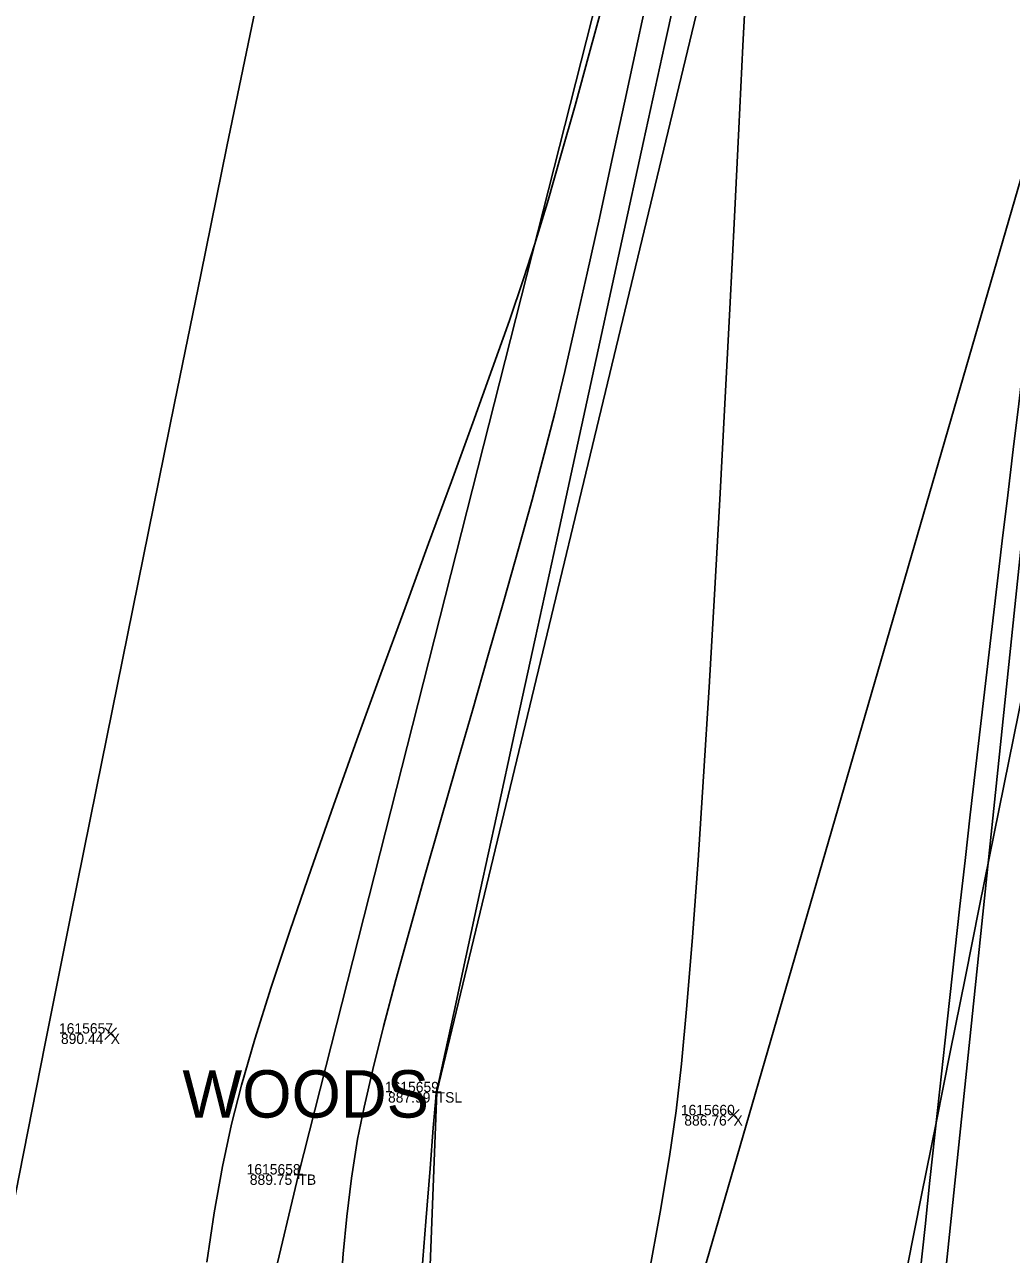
# Model space of a CAD drawing. Extents: x 1957117 to 1971063, y 701601 to 715861.
# Drawn here: x 1962847.45 to 1962880.75, y 704038.02 to 704079.53 of the extents above; entities that cross this region are included whole.
import ezdxf

# ---------------------------------------------------------------- set-up
doc = ezdxf.new("R2010")
doc.units = 0
for name, color, linetype in [('AP_X_Lights', 7, 'Continuous'), ('DT_X_Break_Line', 7, 'Continuous'), ('DT_X_Contour_Major', 7, 'Continuous'), ('DT_X_Contour_Minor', 7, 'Continuous'), ('DT_X_TIN_Hull', 7, 'Continuous'), ('GE_X_CL_20', 7, 'Continuous'), ('HY_X_Water_Edge', 7, 'Continuous'), ('PV_P_Drive', 7, 'Continuous'), ('PV_P_Shoulder', 7, 'Continuous'), ('RS_Raster1', 7, 'Continuous'), ('RW_X_Esmt_RR', 7, 'Continuous'), ('RW_X_Fee_RW', 7, 'Continuous'), ('SC_Scratch1', 7, 'Continuous'), ('VG_X_Text', 7, 'Continuous')]:
    doc.layers.add(name, color=color, linetype=linetype)

msp = doc.modelspace()

# ---------------------------------------------------------------- linework, layer by layer
at = {"layer": 'AP_X_Lights'}
for p, q in [((1962850.162, 704045.276), (1962850.55, 704045.666)), ((1962850.162, 704045.666), (1962850.55, 704045.276)), ((1962871.181, 704042.521), (1962871.569, 704042.911)), ((1962871.181, 704042.911), (1962871.569, 704042.521))]:
    msp.add_line(p, q, dxfattribs=at)
at = {"layer": 'DT_X_Break_Line'}
for points in [[(1962943.949, 704328.022), (1962905.467, 704230.979), (1962897.382, 704180.529), (1962884.517, 704141.123), (1962873.17, 704092.531), (1962861.357, 704043.493), (1962859.494, 703994.644), (1962847.336, 703945.791), (1962836.6, 703895.416), (1962825.781, 703849.035), (1962810.838, 703749.706), (1962817.97, 703697.316), (1962817.962, 703593.874), (1962775.136, 703505.909), (1962781.746, 703450.546)], [(1962773.34, 703451.658), (1962770.93, 703504.314), (1962788.88, 703601.143), (1962786.588, 703649.417), (1962805.729, 703698.412), (1962807.65, 703752.461), (1962811.117, 703798.827), (1962819.396, 703847.658), (1962831.04, 703896.555), (1962840.848, 703945.281), (1962846.53, 703997.82), (1962856.691, 704040.715), (1962869.943, 704092.882), (1962875.651, 704142.958), (1962884.844, 704183.087), (1962898.502, 704228.866), (1962909.862, 704285.214)]]:
    msp.add_lwpolyline(points, dxfattribs=at)
at = {"layer": 'DT_X_Contour_Major'}
msp.add_lwpolyline([(1962866.986, 704080.301), (1962866.508, 704078.539), (1962866.026, 704076.792), (1962865.55, 704075.104), (1962865.092, 704073.522), (1962864.662, 704072.092), (1962864.291, 704070.945), (1962863.809, 704069.537), (1962863.231, 704067.905), (1962862.574, 704066.083), (1962861.853, 704064.108), (1962861.086, 704062.014), (1962860.289, 704059.837), (1962859.477, 704057.614), (1962858.668, 704055.38), (1962857.877, 704053.169), (1962857.121, 704051.019), (1962856.415, 704048.964), (1962855.777, 704047.041), (1962855.223, 704045.284), (1962854.768, 704043.73), (1962854.429, 704042.413), (1962854.128, 704040.985), (1962853.853, 704039.425), (1962853.6, 704037.756)], dxfattribs=at)
msp.add_lwpolyline([(1962866.986, 704080.301), (1962866.508, 704078.539), (1962866.026, 704076.792), (1962865.55, 704075.104), (1962865.092, 704073.522), (1962864.662, 704072.092), (1962864.291, 704070.945), (1962863.809, 704069.537), (1962863.231, 704067.905), (1962862.574, 704066.083), (1962861.853, 704064.108), (1962861.086, 704062.014), (1962860.289, 704059.837), (1962859.477, 704057.614), (1962858.668, 704055.38), (1962857.877, 704053.169), (1962857.121, 704051.019), (1962856.415, 704048.964), (1962855.777, 704047.041), (1962855.223, 704045.284), (1962854.768, 704043.73), (1962854.429, 704042.413), (1962854.128, 704040.985), (1962853.853, 704039.425), (1962853.6, 704037.756)], dxfattribs=at)
at = {"layer": 'DT_X_Contour_Minor'}
for points in [[(1962869.719, 704081.883), (1962869.048, 704078.816), (1962868.34, 704075.577), (1962867.608, 704072.223), (1962866.863, 704068.81), (1962866.119, 704065.396), (1962865.387, 704062.037), (1962864.679, 704058.79), (1962864.009, 704055.711), (1962863.388, 704052.858), (1962862.828, 704050.286), (1962862.342, 704048.054), (1962861.943, 704046.218), (1962861.642, 704044.835), (1962861.452, 704043.96), (1962861.385, 704043.652), (1962861.361, 704043.567), (1962861.338, 704043.482), (1962861.313, 704043.168), (1962861.244, 704042.29), (1962861.135, 704040.919), (1962860.993, 704039.127), (1962860.822, 704036.987)], [(1962869.719, 704081.883), (1962869.048, 704078.816), (1962868.34, 704075.577), (1962867.608, 704072.223), (1962866.863, 704068.81), (1962866.119, 704065.396), (1962865.387, 704062.037), (1962864.679, 704058.79), (1962864.009, 704055.711), (1962863.388, 704052.858), (1962862.828, 704050.286), (1962862.342, 704048.054), (1962861.943, 704046.218), (1962861.642, 704044.835), (1962861.452, 704043.96), (1962861.385, 704043.652), (1962861.361, 704043.567), (1962861.338, 704043.482), (1962861.313, 704043.168), (1962861.244, 704042.29), (1962861.135, 704040.919), (1962860.993, 704039.127), (1962860.822, 704036.987)], [(1962871.819, 704081.358), (1962871.692, 704078.811), (1962871.554, 704076.022), (1962871.405, 704073.043), (1962871.247, 704069.929), (1962871.081, 704066.73), (1962870.908, 704063.501), (1962870.73, 704060.293), (1962870.548, 704057.159), (1962870.362, 704054.152), (1962870.176, 704051.325), (1962869.989, 704048.73), (1962869.802, 704046.42), (1962869.619, 704044.448), (1962869.438, 704042.866), (1962869.211, 704041.319), (1962868.895, 704039.445), (1962868.5, 704037.289)], [(1962871.819, 704081.358), (1962871.692, 704078.811), (1962871.554, 704076.022), (1962871.405, 704073.043), (1962871.247, 704069.929), (1962871.081, 704066.73), (1962870.908, 704063.501), (1962870.73, 704060.293), (1962870.548, 704057.159), (1962870.362, 704054.152), (1962870.176, 704051.325), (1962869.989, 704048.73), (1962869.802, 704046.42), (1962869.619, 704044.448), (1962869.438, 704042.866), (1962869.211, 704041.319), (1962868.895, 704039.445), (1962868.5, 704037.289)], [(1962868.579, 704081.017), (1962868.144, 704078.98), (1962867.707, 704076.944), (1962867.273, 704074.939), (1962866.848, 704072.993), (1962866.436, 704071.138), (1962866.045, 704069.402), (1962865.678, 704067.817), (1962865.341, 704066.412), (1962864.989, 704065.024), (1962864.578, 704063.487), (1962864.12, 704061.828), (1962863.624, 704060.072), (1962863.1, 704058.246), (1962862.561, 704056.376), (1962862.015, 704054.489), (1962861.473, 704052.61), (1962860.947, 704050.766), (1962860.446, 704048.984), (1962859.981, 704047.288), (1962859.562, 704045.706), (1962859.2, 704044.264), (1962858.905, 704042.988), (1962858.689, 704041.904), (1962858.479, 704040.588), (1962858.32, 704039.302), (1962858.2, 704038.04), (1962858.109, 704036.795)], [(1962868.579, 704081.017), (1962868.144, 704078.98), (1962867.707, 704076.944), (1962867.273, 704074.939), (1962866.848, 704072.993), (1962866.436, 704071.138), (1962866.045, 704069.402), (1962865.678, 704067.817), (1962865.341, 704066.412), (1962864.989, 704065.024), (1962864.578, 704063.487), (1962864.12, 704061.828), (1962863.624, 704060.072), (1962863.1, 704058.246), (1962862.561, 704056.376), (1962862.015, 704054.489), (1962861.473, 704052.61), (1962860.947, 704050.766), (1962860.446, 704048.984), (1962859.981, 704047.288), (1962859.562, 704045.706), (1962859.2, 704044.264), (1962858.905, 704042.988), (1962858.689, 704041.904), (1962858.479, 704040.588), (1962858.32, 704039.302), (1962858.2, 704038.04), (1962858.109, 704036.795)]]:
    msp.add_lwpolyline(points, dxfattribs=at)
at = {"layer": 'DT_X_TIN_Hull'}
msp.add_lwpolyline([(1962804.686, 703399.836), (1962817.962, 703593.874), (1962817.97, 703697.316), (1962826.397, 703745.681), (1962828.582, 703804.235), (1962836.461, 703844.734), (1962850.687, 703896.004), (1962867.251, 703938.846), (1962873.848, 703992.355), (1962884.135, 704091.371), (1962891.241, 704140.854), (1962897.382, 704180.529), (1962905.467, 704230.979), (1962909.862, 704285.214)], dxfattribs=at)
at = {"layer": 'GE_X_CL_20'}
msp.add_arc((1968466.781, 702923.066), 5729.578, 166.495347, 177.813939, dxfattribs=at)
at = {"layer": 'HY_X_Water_Edge'}
msp.add_spline([(1963191.723, 701994.048), (1963062.047, 702441.167), (1962863.491, 703169.356), (1962827.53, 703438.691), (1962823.213, 703537.412), (1962817.962, 703593.874), (1962817.97, 703697.316), (1962828.582, 703804.235), (1962836.461, 703844.734), (1962850.687, 703896.004), (1962867.251, 703938.846), (1962873.848, 703992.355), (1962884.135, 704091.371), (1962891.241, 704140.854), (1962897.382, 704180.529), (1962905.467, 704230.979), (1962943.949, 704328.022), (1962948.537, 704378.842), (1962964.114, 704426.264), (1963004.885, 704570.73), (1963042.054, 704716.522), (1963062.038, 704814.417), (1963072.171, 704860.237), (1963090.023, 704956.798), (1963107.066, 705031.783), (1963133.773, 705105.742), (1963148.685, 705206.74), (1963175.48, 705301.059), (1963191.635, 705353.417), (1963210.988, 705447.286), (1963219.532, 705497.27), (1963230.124, 705549.475), (1963251.052, 705591.159), (1963275.289, 705693.429), (1963292.982, 705784.032), (1963302.841, 705839.645), (1963335.126, 705936.766), (1963359.752, 706046.75), (1963389.133, 706177.299), (1963417.827, 706273.456), (1963475.868, 706451.902), (1963533.782, 706640.53), (1963553.86, 706696.984), (1963580.184, 706715.425), (1963609.172, 706718.73), (1963617.062, 706714.691), (1963619.447, 706694.678), (1963564.282, 706533.07), (1963531.853, 706395.229), (1963434.4, 706006.96), (1963354.09, 705679.186), (1963237.513, 705206.07), (1963167.369, 704892.962), (1963059.145, 704434.176), (1962907.914, 703908.742), (1962877.458, 703703.326), (1962898.357, 703412.121), (1962942.65, 703052.267), (1963048.963, 702674.866), (1963191.468, 702189.666), (1963245.396, 702019.832)], degree=3, dxfattribs=at)
at = {"layer": 'PV_P_Drive'}
for p, q in [((1962861.211, 704043.493), (1962861.503, 704043.493)), ((1962861.357, 704043.639), (1962861.357, 704043.347)), ((1962861.357, 704043.493), (1962861.357, 704043.493)), ((1962856.691, 704040.861), (1962856.691, 704040.569)), ((1962856.545, 704040.715), (1962856.837, 704040.715)), ((1962856.691, 704040.715), (1962856.691, 704040.715))]:
    msp.add_line(p, q, dxfattribs=at)
at = {"layer": 'RW_X_Esmt_RR'}
for radius, start, end in [(5759.578, 166.4953469, 172.9409494), (5699.578, 166.495347, 172.904425)]:
    msp.add_arc((1968466.781, 702923.066), radius, start, end, dxfattribs=at)
at = {"layer": 'RW_X_Fee_RW'}
msp.add_line((1962825.007, 703881.15), (1962894.248, 704119.754), dxfattribs=at)

# ---------------------------------------------------------------- texts
at = {"layer": 'PV_P_Shoulder'}
for s, p in [('890.44', (1962848.678, 704045.121)), ('887.99', (1962859.715, 704043.143)), ('886.76', (1962869.713, 704042.366)), ('889.75', (1962855.051, 704040.365))]:
    msp.add_text(s, height=0.35, dxfattribs=at).set_placement(p)
at = {"layer": 'RS_Raster1'}
for s, p in [('1615657', (1962848.612, 704045.471)), ('1615659', (1962859.61, 704043.493)), ('1615660', (1962869.595, 704042.716)), ('1615658', (1962854.944, 704040.715))]:
    msp.add_text(s, height=0.35, dxfattribs=at).set_placement(p)
at = {"layer": 'SC_Scratch1'}
for s, p in [('X', (1962850.356, 704045.121)), ('TSL', (1962861.357, 704043.143)), ('X', (1962871.375, 704042.366)), ('TB', (1962856.691, 704040.365))]:
    msp.add_text(s, height=0.35, dxfattribs=at).set_placement(p)
at = {"layer": 'VG_X_Text'}
msp.add_text('WOODS', height=1.6, dxfattribs=at).set_placement((1962852.776, 704042.635))

doc.saveas('drawing.dxf')
